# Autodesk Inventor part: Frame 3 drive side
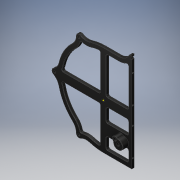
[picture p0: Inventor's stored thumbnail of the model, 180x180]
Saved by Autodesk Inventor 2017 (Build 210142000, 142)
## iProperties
Created: 2016-07
Part Number: Frame 3 drive side
Material: Generic
Document SubType Name: Modeling
Designer: Stan
Density: 1 g/cm^3
Appearance: Glossy - Black
Author: Stan
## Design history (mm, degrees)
sketch "Sketch1"
  geometry: L1 (9.525, 88.9)-(33.07, 88.9); L2 (0, -98.425)-(60.555, -98.425); L3 (9.525, -88.9)-(51.041, -88.9); L4 (6.35, 85.725)-(6.35, 12.7); L5 (-6.35, 85.194)-(-6.35, 12.7); L6 (-6.35, -12.7)-(-6.35, -85.194); L7 (-85.613, -9.525)-(-9.525, -9.525); L8 (9.525, -9.525)-(51.041, -9.525); L9 (-85.613, 9.525)-(-9.525, 9.525); L10 (9.525, 9.525)-(51.041, 9.525); L11 (33.07, 98.425)-(0, 98.425); L12 (54.216, 90.23)-(54.216, 12.7); L13 (54.216, -12.7)-(54.216, -35.468); L14 (54.216, -67.218)-(54.216, -85.725); L15 (60.555, 114.281)-(60.555, 110.471); L16 (60.555, 105.391)-(60.555, -98.425); L17 (51.041, -38.643)-(9.525, -38.643); L18 (6.35, -12.7)-(6.35, -35.468); L19 (6.35, -67.218)-(6.35, -85.725); L20 (51.041, -64.043)-(50.094, -64.043); L21 (38.647, -64.043)-(9.525, -64.043); C1 r 3.175 at (0, 0); C2 r 2.54 at (-104.775, 0); C3 r 2.54 at (-52.387, -90.738); C4 r 2.54 at (-52.387, 90.738); C5 r 3.175 at (44.371, -54.518); C6 r 3.175 at (38.021, -48.168); A1 r 3.175 centre (9.525, -85.725) between (6.35, -85.725) and (9.525, -88.9); A2 r 3.175 centre (9.525, 85.725) between (9.525, 88.9) and (6.35, 85.725); A3 r 3.175 centre (-9.525, -12.7) between (-6.35, -12.7) and (-9.525, -9.525); A4 r 3.175 centre (9.525, -12.7) between (9.525, -9.525) and (6.35, -12.7); A5 r 3.175 centre (51.041, -12.7) between (54.216, -12.7) and (51.041, -9.525); A6 r 3.175 centre (-9.525, 12.7) between (-9.525, 9.525) and (-6.35, 12.7); A7 r 3.175 centre (9.525, 12.7) between (6.35, 12.7) and (9.525, 9.525); A8 r 3.175 centre (51.041, 12.7) between (51.041, 9.525) and (54.216, 12.7); A9 r 98.425 centre (0, 0) between (0, 98.425) and (-29.099, 94.025); A10 r 98.425 centre (0, 0) between (-66.878, 72.213) and (-95.978, 21.812); A11 r 98.425 centre (0, 0) between (-95.978, -21.812) and (-66.878, -72.213); A12 r 98.425 centre (0, 0) between (-29.099, -94.025) and (0, -98.425); A13 r 88.9 centre (0, 0) between (-9.878, 88.35) and (-26.283, 84.926); A14 r 3.175 centre (-9.525, 85.194) between (-6.35, 85.194) and (-9.878, 88.35); A15 r 88.9 centre (0, 0) between (-60.406, 65.225) and (-86.69, 19.701); A16 r 88.9 centre (0, 0) between (-86.69, -19.701) and (-60.406, -65.225); A17 r 88.9 centre (0, 0) between (-26.283, -84.926) and (-9.878, -88.35); A18 r 3.175 centre (-9.525, -85.194) between (-9.878, -88.35) and (-6.35, -85.194); A19 r 6.35 centre (-104.775, 0) between (-107.969, 5.488) and (-107.969, -5.488); A20 r 25.4 centre (-120.746, 27.441) between (-107.969, 5.488) and (-95.978, 21.812); A21 r 34.925 centre (-120.746, 27.441) between (-88.541, 13.928) and (-86.69, 19.701); A22 r 3.175 centre (-85.613, 12.7) between (-88.541, 13.928) and (-85.613, 9.525); A23 r 25.4 centre (-120.746, -27.441) between (-95.978, -21.812) and (-107.969, -5.488); A24 r 34.925 centre (-120.746, -27.441) between (-86.69, -19.701) and (-88.541, -13.928); A25 r 3.175 centre (-85.613, -12.7) between (-85.613, -9.525) and (-88.541, -13.928); A26 r 6.35 centre (-52.387, -90.738) between (-58.737, -90.76) and (-49.232, -96.248); A27 r 25.4 centre (-84.137, -90.849) between (-58.737, -90.76) and (-66.878, -72.213); A28 r 34.925 centre (-84.137, -90.849) between (-50.239, -82.443) and (-60.406, -65.225); A29 r 3.175 centre (-47.157, -81.679) between (-50.239, -82.443) and (-46.278, -84.73); A30 r 25.4 centre (-36.609, -118.29) between (-29.099, -94.025) and (-49.232, -96.248); A31 r 34.925 centre (-36.609, -118.29) between (-26.283, -84.926) and (-46.278, -84.73); A32 r 6.35 centre (-52.387, 90.738) between (-49.232, 96.248) and (-58.737, 90.76); A33 r 25.4 centre (-36.609, 118.29) between (-49.232, 96.248) and (-29.099, 94.025); A34 r 34.925 centre (-36.609, 118.29) between (-46.278, 84.73) and (-26.283, 84.926); A35 r 3.175 centre (-47.157, 81.679) between (-46.278, 84.73) and (-50.239, 82.443); A36 r 25.4 centre (-84.137, 90.849) between (-66.878, 72.213) and (-58.737, 90.76); A37 r 34.925 centre (-84.137, 90.849) between (-60.406, 65.225) and (-50.239, 82.443); A38 r 25.4 centre (33.07, 123.825) between (33.07, 98.425) and (55.067, 111.125); A39 r 34.925 centre (33.07, 123.825) between (33.07, 88.9) and (49.544, 93.029); A40 r 3.175 centre (51.041, 90.23) between (54.216, 90.23) and (49.544, 93.029); A41 r 3.175 centre (51.041, -85.725) between (51.041, -88.9) and (54.216, -85.725); A42 r 6.35 centre (60.555, 107.931) between (60.555, 114.281) and (55.067, 111.125); A43 r 2.54 centre (60.555, 107.931) between (60.555, 110.471) and (60.555, 105.391); A44 r 3.175 centre (9.525, -35.468) between (6.35, -35.468) and (9.525, -38.643); A45 r 3.175 centre (9.525, -67.218) between (9.525, -64.043) and (6.35, -67.218); A46 r 3.175 centre (51.041, -67.218) between (54.216, -67.218) and (51.041, -64.043); A47 r 3.175 centre (51.041, -35.468) between (51.041, -38.643) and (54.216, -35.468); A48 r 11.113 centre (44.371, -54.518) between (38.647, -64.043) and (50.094, -64.043); 4 further points
  constraints: 96 point on circle, 54 centre point, 42 end point, 10 tangent, 5 point on line, 3 equal radius, 2 horizontal
  dimensions: "d17" = 6.35 diameter of C1; "d18" = 60.55515 distance from line of point (0, 0) L16; "d19" = 6.33885 distance between parallel lines of L16 L13; "d20" = 6.33885 distance between parallel lines of L16 L14; "d21" = 9.525 distance between parallel lines of L2 L3; "d22" = 9.525 distance from line of point (0, 0) L8; "d25" = 6.35 diameter of C6; "d27" = 6.35 horizontal distance of C5.centre C6.centre; "d28" = 6.35 horizontal distance of C5.centre C6.centre; "d29" = 9.525 distance from line of L17 C6.centre; "d31" = 34.38151 distance from line of L3 C5.centre; "d32" = 3.175 radius of A44 (derived); "d39" = 22.225 diameter of A48
workplane "Work Plane1"
sketch "Sketch2"
  geometry: L1 (0, 0)-(0, 203.816) reference; C1 r 1.587 at (-3.175, 79.375); C2 r 1.587 at (-3.175, 19.05); C3 r 1.587 at (-3.175, 117.475); C4 r 1.588 at (-3.175, 177.8); 3 further points
  constraints: 4 centre point
  dimensions: "d2" = 3.175 diameter of C1; "d3" = 3.175 diameter of C3; "d4" = 3.175 diameter of C4; "d5" = 3.175 diameter of C2; "d6" = 60.325 distance of C1.centre C2.centre; "d7" = 9.525 vertical distance of point (-6.35, 88.9) C1.centre; "d8" = 9.525 vertical distance of C3.centre point (-6.35, 107.95); "d9" = 60.325 distance of C4.centre C3.centre; "d10" = 3.175 distance from line of L1 C4.centre; "d11" = 3.175 distance from line of L1 C3.centre; "d12" = 3.175 distance from line of L1 C1.centre; "d13" = 3.175 distance from line of L1 C2.centre
extrude "Extrusion3" join sketch "Sketch1" distance "d33" = 6.35; taper "d34" = 0 deg
fillet "Fillet2" dims "d35" = 0.79375
extrude "Extrusion4" cut sketch "Sketch2" distance "d36" = 6.35; taper "d37" = 0 deg
sketch "Sketch3"
  geometry: 1 further point
fillet "Fillet3" dims "d41" = 0.79375
fillet "Fillet4" dims "d42" = 0.79375
sketch "Sketch4"
  geometry: C1 r 3.175 at (44.371, -54.518) reference; C2 r 3.175 at (38.021, -48.168) reference; C3 r 3.175 at (38.021, -48.168); C4 r 3.175 at (44.371, -54.518); A1 r 10.319 centre (44.371, -54.518) between (34.137, -53.193) and (43.045, -44.285); A2 r 6.35 centre (38.021, -48.168) between (43.045, -44.285) and (34.137, -53.193); 1 further point
  constraints: 4 centre point, 4 coincident, 4 point on circle, 2 concentric
  dimensions: "d43" = 12.7 diameter of A2
extrude "Extrusion5" join sketch "Sketch4" distance "d44" = 12.7; taper "d45" = 0 deg
fillet "Fillet5" dims "d46" = 0.79375
body "Solid1"
other parameters: "d23" = 6.35, "d30" = 9.525
